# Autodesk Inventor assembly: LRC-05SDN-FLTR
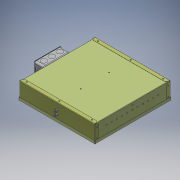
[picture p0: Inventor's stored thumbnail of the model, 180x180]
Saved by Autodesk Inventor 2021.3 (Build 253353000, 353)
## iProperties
description: 0:0:Super Shallow 5-6" Downlight - COB LED
manufacturer: 0:0:The Kirlin Company
model: 0:0:LRC-05SDN
url: 0:0:
Part Number: LRC-05SDN-FLTR
Document SubType Name: Assembly
Designer: JChurch
load_classification: Lighting
motor: 0 ul
Author: JChurch
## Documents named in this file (6)
- X:\Revit Files\0000-Un-Zipped\COB\LRC-05SDN-FLT\LRC-05SDN-FLTR.iam
- X:\INVENTOR\830\830399-00-00.ipt
- X:\INVENTOR\885\885000-00-00.iam
- X:\INVENTOR\750\750938-00-XX.iam
- X:\INVENTOR\KIRLIN_ENG\725\725075-02-00.ipt
- X:\Revit Files\0000-Un-Zipped\COB\LRC-05SDN-FLT\LRC-05SDN-FLTR_Substitute_1.ipt
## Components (5 placed, 5 different names)
1. 830399-00-00:1 — Mate:1, Mate:2, Mate:3, Mate:4, Mate:5, Angle:1, Insert:2
2. 885000-00-00:1 [sub-assembly] — Mate:4, Mate:5, Angle:1
3. 750938-00-XX:1 [sub-assembly] — Insert:1, Insert:2
4. 725075-02-00:1 — Insert:1
5. LRC-05SDN-FLTR_Substitute_1:1
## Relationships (8: Mate 5, Insert 2, Angle 1)
- Mate:1: 830399-00-00:1
- Mate:2: 830399-00-00:1
- Mate:3: 830399-00-00:1
- Mate:4: 830399-00-00:1 ↔ 885000-00-00:1
- Mate:5: 830399-00-00:1 ↔ 885000-00-00:1
- Angle:1: 830399-00-00:1 ↔ 885000-00-00:1
- Insert:1: 750938-00-XX:1 ↔ 725075-02-00:1
- Insert:2: 830399-00-00:1 ↔ 750938-00-XX:1
